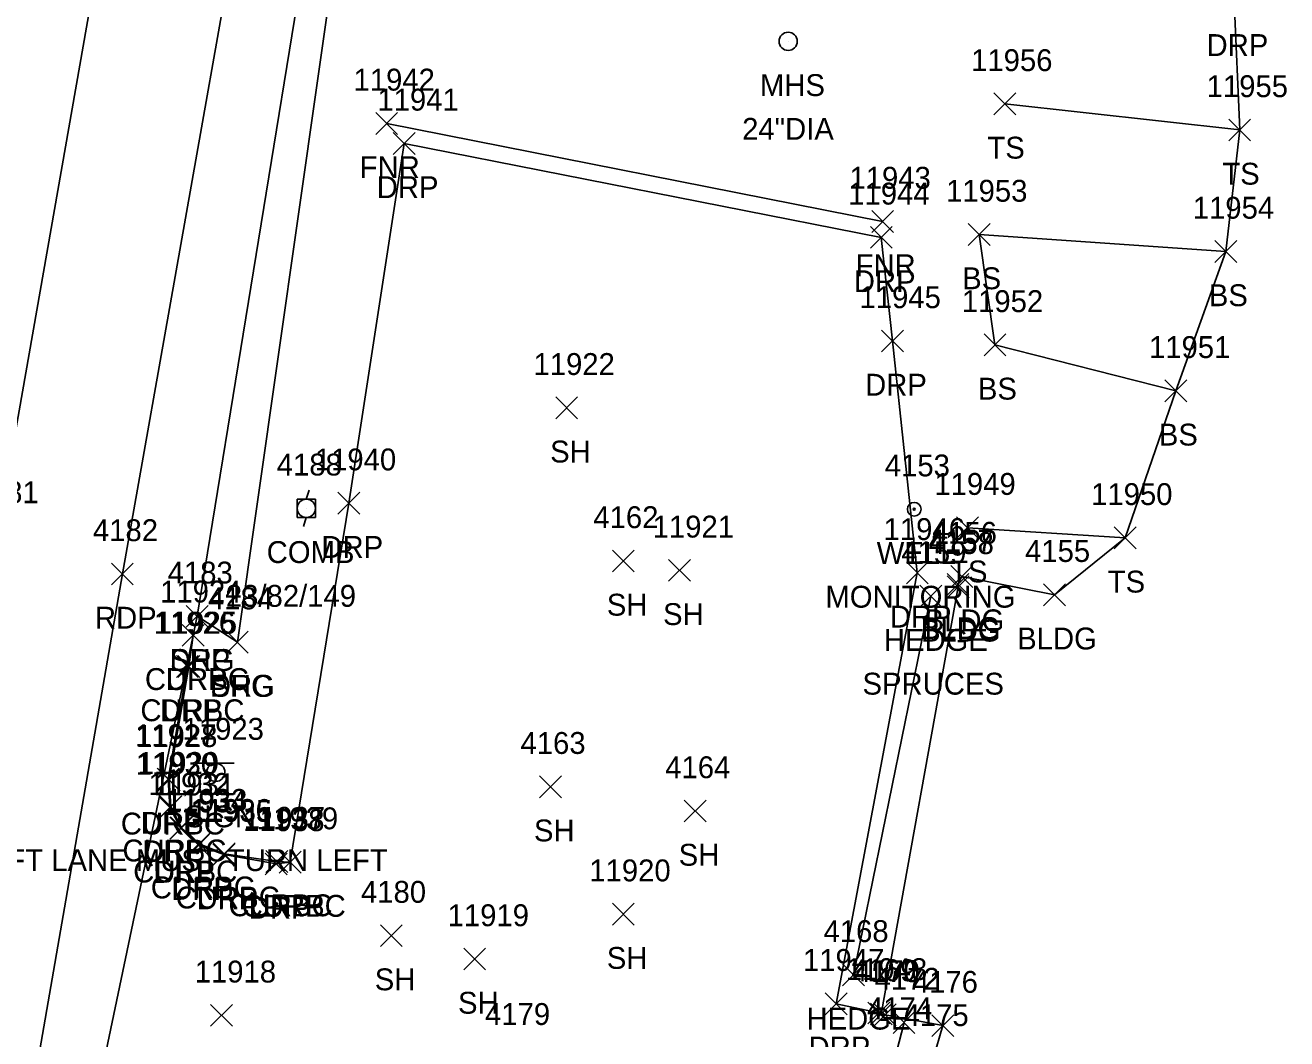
# Model space of a CAD drawing. Extents: x 1769141 to 1770911, y 735471 to 741449.
# Drawn here: x 1770564.6 to 1770679.9, y 738451.6 to 738544.3 of the extents above; entities that cross this region are included whole.
import ezdxf

# ---------------------------------------------------------------- set-up
doc = ezdxf.new("R2010")
doc.units = 0
for name, color, linetype in [('L_A', 7, 'Continuous'), ('L_C', 7, 'Continuous'), ('L_I', 7, 'Continuous'), ('L_TIC', 7, 'Continuous'), ('LAHR', 7, 'Continuous'), ('LBC', 7, 'Continuous'), ('LBF', 7, 'Continuous'), ('LELB', 7, 'Continuous'), ('LFNC', 7, 'Continuous'), ('LSOGP', 7, 'Continuous'), ('P_A', 7, 'Continuous'), ('P_I', 7, 'Continuous'), ('P_TIC', 7, 'Continuous'), ('PET', 7, 'Continuous'), ('PRC', 7, 'Continuous'), ('PSP', 7, 'Continuous'), ('PSU', 7, 'Continuous'), ('R_A', 7, 'Continuous'), ('R_I', 7, 'Continuous'), ('R_TIC', 7, 'Continuous'), ('RC', 7, 'Continuous'), ('RDG', 7, 'Continuous'), ('RDP', 7, 'Continuous'), ('S_A', 7, 'Continuous'), ('S_C', 7, 'Continuous'), ('S_I', 7, 'Continuous'), ('SSGN', 7, 'Continuous'), ('U_A', 7, 'Continuous'), ('U_C', 7, 'Continuous'), ('U_I', 7, 'Continuous'), ('UP', 7, 'Continuous'), ('USMH', 7, 'Continuous'), ('UWW', 7, 'Continuous')]:
    doc.layers.add(name, color=color, linetype=linetype)

msp = doc.modelspace()

# ---------------------------------------------------------------- linework, layer by layer
at = {"layer": 'L_TIC'}
for points in [[(1770653.11, 738536.11), (1770655.11, 738538.11)], [(1770655.11, 738536.11), (1770653.11, 738538.11)], [(1770596.61, 738534.33), (1770598.61, 738536.33)], [(1770598.61, 738534.33), (1770596.61, 738536.33)], [(1770674.58, 738533.73), (1770676.58, 738535.73)], [(1770676.58, 738533.73), (1770674.58, 738535.73)], [(1770641.94, 738525.36), (1770643.94, 738527.36)], [(1770643.94, 738525.36), (1770641.94, 738527.36)], [(1770650.77, 738524.17), (1770652.77, 738526.17)], [(1770652.77, 738524.17), (1770650.77, 738526.17)], [(1770673.32, 738522.62), (1770675.32, 738524.62)], [(1770675.32, 738522.62), (1770673.32, 738524.62)], [(1770652.21, 738514.08), (1770654.21, 738516.08)], [(1770654.21, 738514.08), (1770652.21, 738516.08)], [(1770668.75, 738509.88), (1770670.75, 738511.88)], [(1770670.75, 738509.88), (1770668.75, 738511.88)], [(1770613.06, 738508.33), (1770615.06, 738510.33)], [(1770615.06, 738508.33), (1770613.06, 738510.33)], [(1770649.7, 738497.37), (1770651.7, 738499.37)], [(1770651.7, 738497.37), (1770649.7, 738499.37)], [(1770664.11, 738496.44), (1770666.11, 738498.44)], [(1770666.11, 738496.44), (1770664.11, 738498.44)], [(1770618.24, 738494.33), (1770620.24, 738496.33)], [(1770620.24, 738494.33), (1770618.24, 738496.33)], [(1770623.38, 738493.47), (1770625.38, 738495.47)], [(1770625.38, 738493.47), (1770623.38, 738495.47)], [(1770648.83, 738492.19), (1770650.83, 738494.19)], [(1770650.83, 738492.19), (1770648.83, 738494.19)], [(1770648.85, 738491.96), (1770650.85, 738493.96)], [(1770650.85, 738491.96), (1770648.85, 738493.96)], [(1770649.19, 738492.9), (1770651.19, 738494.9)], [(1770651.19, 738492.9), (1770649.19, 738494.9)], [(1770646.35, 738491.11), (1770648.35, 738493.11)], [(1770648.35, 738491.11), (1770646.35, 738493.11)], [(1770657.65, 738491.24), (1770659.65, 738493.24)], [(1770659.65, 738491.24), (1770657.65, 738493.24)], [(1770611.58, 738473.69), (1770613.58, 738475.69)], [(1770613.58, 738473.69), (1770611.58, 738475.69)], [(1770624.81, 738471.47), (1770626.81, 738473.47)], [(1770626.81, 738471.47), (1770624.81, 738473.47)], [(1770618.24, 738462.04), (1770620.24, 738464.04)], [(1770620.24, 738462.04), (1770618.24, 738464.04)], [(1770597.03, 738460.08), (1770599.03, 738462.08)], [(1770599.03, 738460.08), (1770597.03, 738462.08)], [(1770604.65, 738457.94), (1770606.65, 738459.94)], [(1770606.65, 738457.94), (1770604.65, 738459.94)], [(1770639.28, 738456.49), (1770641.28, 738458.49)], [(1770641.28, 738456.49), (1770639.28, 738458.49)], [(1770581.52, 738452.79), (1770583.52, 738454.79)], [(1770583.52, 738452.79), (1770581.52, 738454.79)], [(1770641.82, 738452.91), (1770643.82, 738454.91)], [(1770643.82, 738452.91), (1770641.82, 738454.91)], [(1770642.17, 738452.83), (1770644.17, 738454.83)], [(1770644.17, 738452.83), (1770642.17, 738454.83)], [(1770643.9, 738452.13), (1770645.9, 738454.13)], [(1770645.9, 738452.13), (1770643.9, 738454.13)], [(1770647.45, 738451.85), (1770649.45, 738453.85)], [(1770649.45, 738451.85), (1770647.45, 738453.85)], [(1770647.45, 738451.85), (1770649.45, 738453.85)], [(1770649.45, 738451.85), (1770647.45, 738453.85)]]:
    msp.add_lwpolyline(points, dxfattribs=at)
at = {"layer": 'LAHR'}
msp.add_lwpolyline([(1770647.35, 738492.11), (1770640.28, 738457.49)], dxfattribs=at)
at = {"layer": 'LBC'}
msp.add_lwpolyline([(1770658.65, 738492.24), (1770650.19, 738493.9), (1770649.83, 738493.19), (1770649.85, 738492.96), (1770642.82, 738453.91), (1770643.17, 738453.83), (1770648.45, 738452.85)], dxfattribs=at)
at = {"layer": 'LBF'}
msp.add_lwpolyline([(1770644.9, 738453.13), (1770644.2, 738450.43), (1770647.55, 738449.81), (1770648.45, 738452.85)], dxfattribs=at)
at = {"layer": 'LELB'}
for points in [[(1770675.58, 738534.73), (1770654.11, 738537.11)], [(1770669.75, 738510.88), (1770653.21, 738515.08), (1770651.77, 738525.17), (1770674.32, 738523.62)], [(1770650.7, 738498.37), (1770665.11, 738497.44)]]:
    msp.add_lwpolyline(points, dxfattribs=at)
at = {"layer": 'LFNC'}
msp.add_lwpolyline([(1770597.61, 738535.33), (1770642.94, 738526.36)], dxfattribs=at)
at = {"layer": 'LSOGP'}
msp.add_lwpolyline([(1770647.55, 738449.81), (1770648.45, 738452.85), (1770643.17, 738453.83), (1770642.82, 738453.91), (1770649.85, 738492.96), (1770649.83, 738493.19), (1770650.19, 738493.9), (1770658.65, 738492.24), (1770665.11, 738497.44), (1770669.75, 738510.88), (1770674.32, 738523.62), (1770675.58, 738534.73), (1770675.06, 738546.49)], dxfattribs=at)
at = {"layer": 'P_TIC'}
for points in [[(1770572.45, 738493.14), (1770574.45, 738495.14)], [(1770574.45, 738493.14), (1770572.45, 738495.14)], [(1770579.29, 738489.27), (1770581.29, 738491.27)], [(1770581.29, 738489.27), (1770579.29, 738491.27)], [(1770582.96, 738486.91), (1770584.96, 738488.91)], [(1770584.96, 738486.91), (1770582.96, 738488.91)]]:
    msp.add_lwpolyline(points, dxfattribs=at)
at = {"layer": 'PET'}
msp.add_lwpolyline([(1770519.35, 738183.15), (1770528.05, 738233.56), (1770539.53, 738299.08), (1770548.74, 738352.36), (1770557.68, 738403.13), (1770564.13, 738440.46), (1770573.45, 738494.14), (1770584.12, 738554.39), (1770592.19, 738600.77), (1770602.63, 738660.09), (1770612.1, 738713.05), (1770618.25, 738747.4), (1770627.86, 738802.06), (1770637.55, 738855.14), (1770646.46, 738901.9), (1770653.63, 738941.04), (1770664.31, 738997.45), (1770673.48, 739046.36)], dxfattribs=at)
at = {"layer": 'PRC'}
msp.add_lwpolyline([(1770507.77, 738186.68), (1770516.39, 738236.25), (1770527.92, 738302.48), (1770537.02, 738354.2), (1770545.79, 738405.62), (1770552.19, 738442.28), (1770561.98, 738497.61), (1770572.5, 738557.36), (1770580.07, 738602.32), (1770591.07, 738663.64), (1770600.38, 738716.09), (1770606.4, 738749.37), (1770616.02, 738804.08), (1770625.81, 738857.85), (1770633.75, 738899.85), (1770641.85, 738943.04), (1770652.79, 739000.55), (1770661.76, 739049.09)], dxfattribs=at)
at = {"layer": 'PSP'}
msp.add_lwpolyline([(1770531.42, 738212.51), (1770539.31, 738265.32), (1770544.7, 738296.55), (1770554.36, 738351.24), (1770563.47, 738402.29), (1770569.65, 738439.48), (1770580.29, 738490.27), (1770590.59, 738553.45), (1770592.36, 738563.69), (1770605.67, 738640.79), (1770608.73, 738658.33), (1770613.7, 738685.31)], dxfattribs=at)
at = {"layer": 'PSU'}
msp.add_lwpolyline([(1770583.96, 738487.91), (1770593.22, 738552.73), (1770593.02, 738560.07), (1770592.35, 738562.09), (1770592.36, 738563.69)], dxfattribs=at)
at = {"layer": 'R_TIC'}
for points in [[(1770598.21, 738532.5), (1770600.21, 738534.5)], [(1770600.21, 738532.5), (1770598.21, 738534.5)], [(1770641.82, 738523.91), (1770643.82, 738525.91)], [(1770643.82, 738523.91), (1770641.82, 738525.91)], [(1770642.85, 738514.44), (1770644.85, 738516.44)], [(1770644.85, 738514.44), (1770642.85, 738516.44)], [(1770593.15, 738499.61), (1770595.15, 738501.61)], [(1770595.15, 738499.61), (1770593.15, 738501.61)], [(1770645.11, 738493.24), (1770647.11, 738495.24)], [(1770647.11, 738493.24), (1770645.11, 738495.24)], [(1770579.29, 738489.27), (1770581.29, 738491.27)], [(1770581.29, 738489.27), (1770579.29, 738491.27)], [(1770578.92, 738487.53), (1770580.92, 738489.53)], [(1770580.92, 738487.53), (1770578.92, 738489.53)], [(1770578.92, 738487.53), (1770580.92, 738489.53)], [(1770580.92, 738487.53), (1770578.92, 738489.53)], [(1770582.96, 738486.91), (1770584.96, 738488.91)], [(1770584.96, 738486.91), (1770582.96, 738488.91)], [(1770578.39, 738484.68), (1770580.39, 738486.68)], [(1770580.39, 738484.68), (1770578.39, 738486.68)], [(1770578.52, 738484.68), (1770580.52, 738486.68)], [(1770580.52, 738484.68), (1770578.52, 738486.68)], [(1770576.63, 738474.39), (1770578.63, 738476.39)], [(1770578.63, 738474.39), (1770576.63, 738476.39)], [(1770576.73, 738474.32), (1770578.73, 738476.32)], [(1770578.73, 738474.32), (1770576.73, 738476.32)], [(1770576.78, 738471.79), (1770578.78, 738473.79)], [(1770578.78, 738471.79), (1770576.78, 738473.79)], [(1770576.88, 738471.86), (1770578.88, 738473.86)], [(1770578.88, 738471.86), (1770576.88, 738473.86)], [(1770577.78, 738469.9), (1770579.78, 738471.9)], [(1770579.78, 738469.9), (1770577.78, 738471.9)], [(1770577.85, 738469.94), (1770579.85, 738471.94)], [(1770579.85, 738469.94), (1770577.85, 738471.94)], [(1770579.42, 738468.35), (1770581.42, 738470.35)], [(1770581.42, 738468.35), (1770579.42, 738470.35)], [(1770579.47, 738468.48), (1770581.47, 738470.48)], [(1770581.47, 738468.48), (1770579.47, 738470.48)], [(1770581.73, 738467.48), (1770583.73, 738469.48)], [(1770583.73, 738467.48), (1770581.73, 738469.48)], [(1770581.75, 738467.56), (1770583.75, 738469.56)], [(1770583.75, 738467.56), (1770581.75, 738469.56)], [(1770586.51, 738466.63), (1770588.51, 738468.63)], [(1770588.51, 738466.63), (1770586.51, 738468.63)], [(1770586.57, 738466.85), (1770588.57, 738468.85)], [(1770588.57, 738466.85), (1770586.57, 738468.85)], [(1770587.78, 738466.8), (1770589.78, 738468.8)], [(1770589.78, 738466.8), (1770587.78, 738468.8)], [(1770587.78, 738466.8), (1770589.78, 738468.8)], [(1770589.78, 738466.8), (1770587.78, 738468.8)], [(1770637.69, 738453.85), (1770639.69, 738455.85)], [(1770639.69, 738453.85), (1770637.69, 738455.85)], [(1770641.6, 738453.01), (1770643.6, 738455.01)], [(1770643.6, 738453.01), (1770641.6, 738455.01)]]:
    msp.add_lwpolyline(points, dxfattribs=at)
at = {"layer": 'RC'}
msp.add_lwpolyline([(1770579.92, 738488.53), (1770579.52, 738485.68), (1770577.73, 738475.32), (1770577.88, 738472.86), (1770578.85, 738470.94), (1770580.47, 738469.48), (1770582.75, 738468.56), (1770587.57, 738467.85), (1770588.78, 738467.8)], dxfattribs=at)
at = {"layer": 'RDG'}
msp.add_lwpolyline([(1770580.29, 738490.27), (1770583.96, 738487.91)], dxfattribs=at)
at = {"layer": 'RDP'}
msp.add_lwpolyline([(1770579.92, 738488.53), (1770579.39, 738485.68), (1770577.63, 738475.39), (1770577.78, 738472.79), (1770578.78, 738470.9), (1770580.42, 738469.35), (1770582.73, 738468.48), (1770587.51, 738467.63), (1770588.78, 738467.8), (1770594.15, 738500.61), (1770599.21, 738533.5), (1770642.82, 738524.91), (1770643.85, 738515.44), (1770646.11, 738494.24), (1770638.69, 738454.85), (1770642.6, 738454.01)], dxfattribs=at)
at = {"layer": 'SSGN'}
for p, q in [((1770580.35, 738476.84), (1770583.68, 738476.84)), ((1770581.99, 738476), (1770581.99, 738476))]:
    msp.add_line(p, q, dxfattribs=at)
msp.add_circle((1770581.99, 738476), 0.833, dxfattribs=at)
at = {"layer": 'UP'}
for p, q in [((1770589.42, 738499.3), (1770589.42, 738500.97)), ((1770589.42, 738500.97), (1770591.09, 738500.97)), ((1770590.51, 738501.8), (1770590.26, 738500.97)), ((1770591.09, 738500.97), (1770591.09, 738499.3)), ((1770590.26, 738500.14), (1770590.26, 738500.14)), ((1770591.09, 738499.3), (1770589.42, 738499.3)), ((1770590.01, 738498.47), (1770590.26, 738499.3))]:
    msp.add_line(p, q, dxfattribs=at)
msp.add_circle((1770590.26, 738500.14), 0.833, dxfattribs=at)
at = {"layer": 'USMH'}
for p, q in [((1770634.31, 738542.83), (1770634.31, 738542.83)), ((1770635.14, 738542.83), (1770635.14, 738542.83))]:
    msp.add_line(p, q, dxfattribs=at)
msp.add_circle((1770634.31, 738542.83), 0.833, dxfattribs=at)
at = {"layer": 'UWW'}
for radius in [0.625, 0.0833]:
    msp.add_circle((1770645.83, 738500.06), radius, dxfattribs=at)

# ---------------------------------------------------------------- texts
at = {"layer": 'L_A'}
for s, p in [('TS', (1770652.52, 738532.11)), ('FNR', (1770595.14, 738530.33)), ('TS', (1770673.99, 738529.73)), ('FNR', (1770640.47, 738521.36)), ('BS', (1770650.21, 738520.17)), ('BS', (1770672.76, 738518.62)), ('BS', (1770651.65, 738510.08)), ('BS', (1770668.19, 738505.88)), ('SH', (1770612.55, 738504.33)), ('TS', (1770649.11, 738493.37)), ('TS', (1770663.52, 738492.44)), ('SH', (1770617.73, 738490.33)), ('SH', (1770622.87, 738489.47)), ('BLDG', (1770646.78, 738488.9)), ('BLDG', (1770646.42, 738488.19)), ('BLDG', (1770646.45, 738487.96)), ('HEDGE', (1770643.05, 738487.11)), ('BLDG', (1770655.24, 738487.24)), ('SH', (1770611.07, 738469.69)), ('SH', (1770624.3, 738467.47)), ('SH', (1770617.73, 738458.04)), ('SH', (1770596.52, 738456.08)), ('SH', (1770604.13, 738453.94)), ('HEDGE', (1770635.98, 738452.49))]:
    msp.add_text(s, height=2, dxfattribs=at).set_placement(p)
at = {"layer": 'L_C'}
msp.add_text('SPRUCES', height=2, dxfattribs=at).set_placement((1770641.1, 738483.11))
at = {"layer": 'L_I'}
for s, p in [('11956', (1770651.03, 738540.11)), ('11942', (1770594.58, 738538.33)), ('11955', (1770672.56, 738537.73)), ('11943', (1770639.91, 738529.36)), ('11953', (1770648.74, 738528.17)), ('11954', (1770671.29, 738526.62)), ('11952', (1770650.18, 738518.08)), ('11951', (1770667.29, 738513.88)), ('11922', (1770611.03, 738512.33)), ('11949', (1770647.67, 738501.37)), ('11950', (1770662, 738500.44)), ('4162', (1770616.5, 738498.33)), ('11921', (1770621.92, 738497.47)), ('4156', (1770647.44, 738496.9)), ('4157', (1770647.14, 738496.19)), ('4158', (1770647.16, 738495.96)), ('4159', (1770644.65, 738495.11)), ('4155', (1770655.96, 738495.24)), ('4163', (1770609.84, 738477.69)), ('4164', (1770623.07, 738475.47)), ('11920', (1770616.13, 738466.04)), ('4180', (1770595.26, 738464.08)), ('11919', (1770603.18, 738461.94)), ('4168', (1770637.54, 738460.49)), ('11918', (1770580.06, 738456.79)), ('4169', (1770640.07, 738456.91)), ('4170', (1770640.39, 738456.83)), ('4172', (1770642.21, 738456.13)), ('4176', (1770645.7, 738455.85)), ('4176', (1770645.7, 738455.85)), ('4179', (1770606.6, 738452.91)), ('4174', (1770641.51, 738453.43)), ('4175', (1770644.86, 738452.81))]:
    msp.add_text(s, height=2, dxfattribs=at).set_placement(p)
at = {"layer": 'P_A'}
for s, p in [('RDP', (1770570.94, 738489.14)), ('SHP', (1770577.82, 738485.27)), ('SHG', (1770581.5, 738482.91))]:
    msp.add_text(s, height=2, dxfattribs=at).set_placement(p)
at = {"layer": 'P_I'}
for s, p in [('4181', (1770559.85, 738500.61)), ('4182', (1770570.76, 738497.14)), ('4183', (1770577.59, 738493.27)), ('4184', (1770581.27, 738490.91))]:
    msp.add_text(s, height=2, dxfattribs=at).set_placement(p)
at = {"layer": 'R_A'}
for s, p in [('DRP', (1770672.55, 738541.49)), ('DRP', (1770596.7, 738528.5)), ('DRP', (1770640.31, 738519.91)), ('DRP', (1770641.34, 738510.44)), ('DRP', (1770591.64, 738495.61)), ('DRP', (1770643.6, 738489.24)), ('DRG', (1770577.77, 738485.27)), ('CURBC', (1770575.51, 738483.53)), ('DRP', (1770577.41, 738483.53)), ('DRG', (1770581.45, 738482.91)), ('CURBC', (1770575.1, 738480.68)), ('DRP', (1770576.88, 738480.68)), ('CURBC', (1770573.31, 738470.32)), ('DRP', (1770575.12, 738470.39)), ('CURBC', (1770573.46, 738467.86)), ('DRP', (1770575.27, 738467.79)), ('CURBC', (1770574.44, 738465.94)), ('DRP', (1770576.27, 738465.9)), ('CURBC', (1770576.05, 738464.48)), ('DRP', (1770577.91, 738464.35)), ('CURBC', (1770578.33, 738463.56)), ('DRP', (1770580.22, 738463.48)), ('CURBC', (1770583.15, 738462.85)), ('CURBC', (1770584.36, 738462.8)), ('DRP', (1770585, 738462.63)), ('DRP', (1770586.26, 738462.8)), ('DRP', (1770636.17, 738449.85))]:
    msp.add_text(s, height=2, dxfattribs=at).set_placement(p)
at = {"layer": 'R_I'}
for s, p in [('11941', (1770596.76, 738536.5)), ('11944', (1770639.8, 738527.91)), ('11945', (1770640.83, 738518.44)), ('11940', (1770591.04, 738503.61)), ('11946', (1770643.03, 738497.24)), ('4183', (1770577.59, 738493.27)), ('11924', (1770576.9, 738491.53)), ('11924', (1770576.9, 738491.53)), ('4184', (1770581.27, 738490.91)), ('11926', (1770576.32, 738488.68)), ('11925', (1770576.5, 738488.68)), ('11927', (1770574.61, 738478.39)), ('11928', (1770574.7, 738478.32)), ('11930', (1770574.67, 738475.79)), ('11929', (1770574.85, 738475.86)), ('11932', (1770575.83, 738473.94)), ('11931', (1770576.32, 738473.9)), ('11934', (1770577.4, 738472.35)), ('11933', (1770577.44, 738472.48)), ('11936', (1770579.67, 738471.56)), ('11935', (1770579.71, 738471.48)), ('11938', (1770584.49, 738470.63)), ('11937', (1770584.54, 738470.85)), ('11939', (1770585.74, 738470.8)), ('11939', (1770585.74, 738470.8)), ('11947', (1770635.66, 738457.85)), ('11948', (1770639.58, 738457.01))]:
    msp.add_text(s, height=2, dxfattribs=at).set_placement(p)
at = {"layer": 'S_A'}
msp.add_text('SIGN', height=2, dxfattribs=at).set_placement((1770579.13, 738470.98))
at = {"layer": 'S_C'}
msp.add_text('LEFT LANE MUST TURN LEFT', height=2, dxfattribs=at).set_placement((1770559.67, 738466.98))
at = {"layer": 'S_I'}
msp.add_text('11923', height=2, dxfattribs=at).set_placement((1770578.95, 738478.98))
at = {"layer": 'U_A'}
for s, p in [('MHS', (1770631.73, 738537.83)), ('COMB', (1770586.64, 738495.14)), ('WELL', (1770642.4, 738495.06))]:
    msp.add_text(s, height=2, dxfattribs=at).set_placement(p)
at = {"layer": 'U_C'}
for s, p in [('24"DIA', (1770630.1, 738533.83)), ('23/82/149', (1770582.91, 738491.14)), ('MONITORING', (1770637.71, 738491.06))]:
    msp.add_text(s, height=2, dxfattribs=at).set_placement(p)
at = {"layer": 'U_I'}
for s, p in [('4188', (1770587.56, 738503.14)), ('4153', (1770643.14, 738503.06))]:
    msp.add_text(s, height=2, dxfattribs=at).set_placement(p)

doc.saveas('drawing.dxf')
